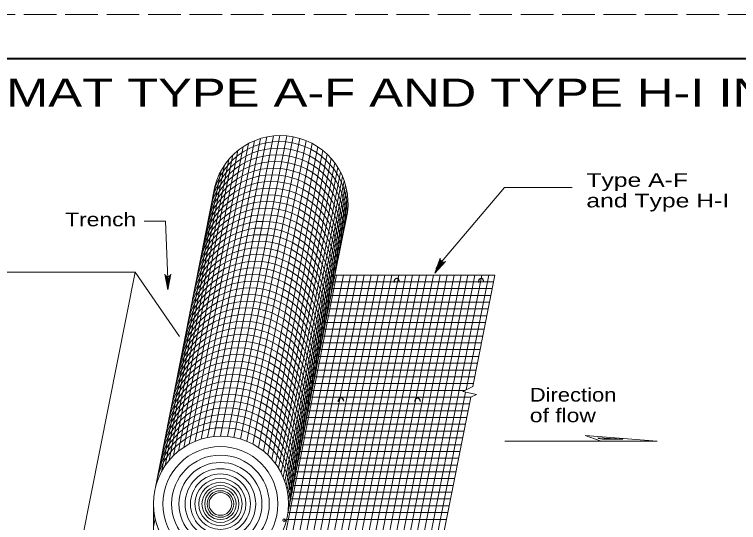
# Model space of a CAD drawing. Extents: x 1083.1 to 1117.1, y 719.4 to 741.4.
# Drawn here: x 1096.82 to 1105.08, y 735.56 to 741.35 of the extents above; entities that cross this region are included whole.
import ezdxf

# ---------------------------------------------------------------- set-up
doc = ezdxf.new("R2010")
doc.units = 0
doc.header["$LTSCALE"] = 0.062
doc.header["$PDMODE"] = 32
doc.header["$PDSIZE"] = 0.031
doc.linetypes.add('LONG_DASHED', pattern=[7.5, 6, -1.5])
doc.layers.add('1', color=7, linetype='Continuous', lineweight=13)

msp = doc.modelspace()

# ---------------------------------------------------------------- linework, layer by layer
at = {"layer": '1', "lineweight": 25}
msp.add_line((1085.12642, 740.85408), (1116.62642, 740.85408), dxfattribs=at)
at = {"layer": '1'}
for p, q in [((1098.88158, 736.48833), (1099.559, 739.91517)), ((1098.94975, 736.513), (1099.62717, 739.93983)), ((1099.0235, 736.53183), (1099.70092, 739.95867)), ((1099.09725, 736.54325), (1099.7745, 739.97008)), ((1099.84792, 739.97425), (1099.17058, 736.54742)), ((1099.25067, 736.544), (1099.928, 739.97083)), ((1100.00208, 739.96008), (1099.32475, 736.53325)), ((1100.07708, 739.94158), (1099.39975, 736.51475)), ((1100.15008, 739.9155), (1099.47275, 736.48883)), ((1099.43008, 739.84658), (1098.75275, 736.41975)), ((1099.49275, 739.88383), (1098.81542, 736.457)), ((1100.21842, 739.88317), (1099.541, 736.4565)), ((1100.28208, 739.845), (1099.60475, 736.41833)), ((1099.31375, 739.75233), (1098.63642, 736.3255)), ((1099.3705, 739.803), (1098.69317, 736.37608)), ((1100.33767, 739.80442), (1099.66042, 736.37767)), ((1100.38833, 739.76), (1099.711, 736.33333)), ((1099.26508, 739.69958), (1098.58775, 736.27275)), ((1100.43392, 739.71225), (1099.75667, 736.28558)), ((1100.47483, 739.66167), (1099.7975, 736.23492)), ((1099.21908, 739.63925), (1098.54175, 736.21233)), ((1100.511, 739.60833), (1099.83367, 736.18167)), ((1099.175, 739.5665), (1098.49758, 736.13958)), ((1100.53925, 739.55833), (1099.862, 736.13175)), ((1100.56325, 739.50792), (1099.88592, 736.08125)), ((1100.58292, 739.45725), (1099.9055, 736.03067)), ((1100.59725, 739.41183), (1099.91983, 735.98525)), ((1099.10767, 739.3925), (1098.43042, 735.96617)), ((1100.60892, 739.36417), (1099.93158, 735.9375)), ((1102.83092, 739.38158), (1103.17883, 739.38158)), ((1100.61792, 739.31358), (1099.94067, 735.88708)), ((1100.62392, 739.25808), (1099.94667, 735.83158)), ((1101.67958, 738.555), (1101.617, 738.40575)), ((1101.68633, 738.54467), (1101.617, 738.40575)), ((1101.69525, 738.5375), (1101.617, 738.40575)), ((1101.70908, 738.53258), (1101.617, 738.40575)), ((1101.72108, 738.5325), (1101.617, 738.40575)), ((1096.7415, 738.418), (1098.1975, 738.418)), ((1098.1975, 738.418), (1097.50425, 734.91067)), ((1098.7055, 737.68467), (1098.1975, 738.418)), ((1098.54892, 738.37575), (1098.57133, 738.21558)), ((1098.56, 738.37033), (1098.57133, 738.21558)), ((1098.59608, 738.37767), (1098.57133, 738.21558)), ((1098.58575, 738.3715), (1098.57133, 738.21558)), ((1098.57133, 738.36875), (1098.57133, 738.21558)), ((1099.82708, 735.00583), (1100.49425, 738.38117)), ((1099.90592, 735.00583), (1100.57317, 738.38117)), ((1099.98483, 735.00583), (1100.652, 738.38117)), ((1100.06375, 735.00583), (1100.73092, 738.38117)), ((1100.14258, 735.00583), (1100.80975, 738.38117)), ((1100.2215, 735.00583), (1100.88867, 738.38117)), ((1100.30033, 735.00583), (1100.9675, 738.38117)), ((1100.37925, 735.00583), (1101.04642, 738.38117)), ((1100.45808, 735.00583), (1101.12533, 738.38117)), ((1100.47708, 738.38117), (1102.2985, 738.38117)), ((1100.537, 735.00583), (1101.20417, 738.38117)), ((1100.61583, 735.00583), (1101.283, 738.38117)), ((1100.69475, 735.00583), (1101.36183, 738.38117)), ((1100.77367, 735.00583), (1101.44075, 738.38117)), ((1100.8525, 735.00583), (1101.51958, 738.38117)), ((1100.93142, 735.00583), (1101.5985, 738.38117)), ((1101.01025, 735.00583), (1101.67733, 738.38117)), ((1101.08917, 735.00583), (1101.75625, 738.38117)), ((1101.168, 735.00583), (1101.83517, 738.38117)), ((1101.24692, 735.00583), (1101.914, 738.38117)), ((1101.32575, 735.00583), (1101.99292, 738.38117)), ((1101.40467, 735.00583), (1102.07175, 738.38117)), ((1101.48358, 735.00583), (1102.15067, 738.38117)), ((1101.97133, 737.07483), (1102.2295, 738.38117)), ((1102.04758, 737.11175), (1102.2985, 738.38117)), ((1100.4625, 738.30692), (1102.28383, 738.30692)), ((1100.44717, 738.22958), (1102.2685, 738.22958)), ((1100.43192, 738.15217), (1102.25325, 738.15217)), ((1100.41667, 738.07483), (1102.23792, 738.07483)), ((1100.40133, 737.99742), (1102.22258, 737.99742)), ((1100.37075, 737.84267), (1102.19208, 737.84267)), ((1100.38608, 737.92008), (1102.20733, 737.92008)), ((1100.3555, 737.76533), (1102.17675, 737.76533)), ((1100.34017, 737.68792), (1102.1615, 737.68792)), ((1100.32483, 737.61058), (1102.14617, 737.61058)), ((1100.30958, 737.53317), (1102.13092, 737.53317)), ((1100.29425, 737.45583), (1102.11558, 737.45583)), ((1100.279, 737.3785), (1102.10025, 737.3785)), ((1100.26367, 737.30108), (1102.085, 737.30108)), ((1100.24842, 737.22375), (1102.06967, 737.22375)), ((1100.23317, 737.14633), (1102.05433, 737.14633)), ((1100.21783, 737.069), (1101.95925, 737.069)), ((1101.56233, 735.00583), (1101.96633, 737.04958)), ((1100.20258, 736.99158), (1102.02375, 736.99158)), ((1101.63133, 735.00583), (1102.02383, 736.99158)), ((1100.18725, 736.91425), (1102.00858, 736.91425)), ((1100.17192, 736.83683), (1101.99325, 736.83683)), ((1100.15667, 736.7595), (1101.97792, 736.7595)), ((1100.12608, 736.60475), (1101.94733, 736.60475)), ((1100.14133, 736.68208), (1101.96267, 736.68208)), ((1100.11075, 736.52733), (1101.932, 736.52733)), ((1100.09542, 736.45), (1101.91675, 736.45)), ((1100.08017, 736.37258), (1101.90142, 736.37258)), ((1100.06492, 736.29525), (1101.88608, 736.29525)), ((1100.04967, 736.21792), (1101.87083, 736.21792)), ((1100.03433, 736.1405), (1101.8555, 736.1405)), ((1100.019, 736.06317), (1101.84017, 736.06317)), ((1100.00375, 735.98575), (1101.825, 735.98575)), ((1099.98842, 735.90842), (1101.80967, 735.90842)), ((1098.40675, 735.77667), (1098.40675, 734.01492)), ((1099.97317, 735.831), (1101.79442, 735.831)), ((1098.40675, 735.71342), (1098.40867, 735.723)), ((1099.95783, 735.75367), (1101.77908, 735.75367)), ((1099.9425, 735.67625), (1101.76375, 735.67625)), ((1098.40675, 735.514), (1098.42542, 735.60842)), ((1099.92775, 735.59892), (1101.7485, 735.59892))]:
    msp.add_line(p, q, dxfattribs=at)
at = {"layer": '1', "linetype": 'LONG_DASHED'}
msp.add_lwpolyline([(1083.12642, 719.35408), (1117.12642, 719.35408), (1117.12642, 741.35408), (1083.12642, 741.35408)], close=True, dxfattribs=at)
at = {"layer": '1', "lineweight": 40}
msp.add_lwpolyline([(1085.12642, 740.85408), (1116.62642, 740.85408), (1116.62642, 719.85408), (1085.12642, 719.85408)], close=True, dxfattribs=at)
msp.add_lwpolyline([(1085.12642, 740.85408), (1116.62642, 740.85408), (1116.62642, 719.85408), (1085.12642, 719.85408)], close=True, dxfattribs=at)
at = {"layer": '1'}
for points in [[(1101.62608, 738.45817), (1102.41108, 739.38158), (1102.83092, 739.38158)], [(1100.61892, 739.09867), (1100.47708, 738.38117), (1099.94075, 735.66767)], [(1098.57417, 738.24617), (1098.54483, 738.997), (1098.30075, 738.997)], [(1101.73783, 738.53992), (1101.617, 738.40575), (1101.67692, 738.576)], [(1098.60675, 738.39258), (1098.57133, 738.21558), (1098.53592, 738.39258)], [(1102.0475, 737.11167), (1101.93375, 737.05667), (1102.08833, 737.02292), (1102.02375, 736.99158)], [(1102.41475, 736.49075), (1104.15083, 736.49075), (1103.32742, 736.55342), (1103.49875, 736.49333)], [(1103.47133, 736.52725), (1103.759, 736.51158), (1103.52583, 736.51158), (1103.47633, 736.522)]]:
    msp.add_lwpolyline(points, dxfattribs=at)
for centre, start, end in [((1101.71466, 738.57027), 171.38675, 307.21287), ((1098.57128, 738.40684), 202.08782, 337.91395)]:
    msp.add_arc(centre, 0.0382, start, end, dxfattribs=at)
for centre, major_axis, start_param, end_param in [((1099.85498, 739.20341), (0.7709, 0), 6.1469612, 9.1769689), ((1099.8414, 739.13534), (-0.77089, 0), 2.9997094, 6.0347974), ((1099.81141, 738.9836), (-0.77089, 0), 2.9997094, 6.0347974), ((1099.8264, 739.05947), (-0.77089, 0), 2.9997094, 6.0347974), ((1099.79642, 738.90772), (-0.77089, 0), 2.9997094, 6.0347974), ((1099.78143, 738.83185), (-0.77089, 0), 2.9997094, 6.0347974), ((1099.76643, 738.75598), (-0.77089, 0), 2.9997094, 6.0347974), ((1099.75144, 738.6801), (-0.77089, 0), 2.9997094, 6.0347974), ((1099.73645, 738.60423), (-0.77089, 0), 2.9997094, 6.0347974), ((1099.72145, 738.52836), (-0.77089, 0), 2.9997094, 6.0347974), ((1099.70646, 738.45248), (-0.77089, 0), 2.9997094, 6.0347974), ((1099.69139, 738.37661), (-0.77089, 0), 2.9997094, 6.0347974), ((1099.67639, 738.30074), (-0.77089, 0), 2.9997094, 6.0347974), ((1099.6614, 738.22487), (-0.77089, 0), 2.9997094, 6.0347974), ((1099.64641, 738.14899), (-0.77089, 0), 2.9997094, 6.0347974), ((1099.61642, 737.99725), (-0.77089, 0), 2.9997094, 6.0347974), ((1099.63141, 738.07312), (-0.77089, 0), 2.9997094, 6.0347974), ((1099.60143, 737.92137), (-0.77089, 0), 2.9997094, 6.0347974), ((1099.58643, 737.8455), (-0.77089, 0), 2.9997094, 6.0347974), ((1099.57144, 737.76963), (-0.77089, 0), 2.9997094, 6.0347974), ((1099.55645, 737.69376), (-0.77089, 0), 2.9997094, 6.0347974), ((1099.54146, 737.61788), (-0.77089, 0), 2.9997094, 6.0347974), ((1099.52646, 737.54201), (-0.77089, 0), 2.9997094, 6.0347974), ((1099.51147, 737.46614), (-0.77089, 0), 2.9997094, 6.0347974), ((1099.49648, 737.39026), (-0.77089, 0), 2.9997094, 6.0347974), ((1099.48148, 737.31439), (-0.77089, 0), 2.9997094, 6.0347974), ((1099.46649, 737.23852), (-0.77089, 0), 2.9997094, 6.0347974), ((1099.43651, 737.08677), (-0.77089, 0), 2.9997094, 6.0347974), ((1099.4515, 737.16264), (-0.77089, 0), 2.9997094, 6.0347974), ((1099.42151, 737.0109), (-0.77089, 0), 2.9997094, 6.0347974), ((1099.40652, 736.93503), (-0.77089, 0), 2.9997094, 6.0347974), ((1099.39153, 736.85915), (-0.77089, 0), 2.9997094, 6.0347974), ((1099.37653, 736.78328), (-0.77089, 0), 2.9997094, 6.0347974), ((1099.36154, 736.70741), (-0.77089, 0), 2.9997094, 6.0347974), ((1099.34655, 736.63153), (-0.77089, 0), 2.9997094, 6.0347974), ((1099.33155, 736.55566), (-0.77089, 0), 2.9997094, 6.0347974), ((1099.31656, 736.47979), (-0.77089, 0), 2.9997094, 6.0347974), ((1099.30157, 736.40392), (-0.77089, 0), 2.9997094, 6.0347974), ((1099.28658, 736.32804), (-0.77089, 0), 2.9997094, 6.0347974), ((1099.27158, 736.25217), (-0.77089, 0), 2.9997094, 6.0347974), ((1099.2416, 736.10042), (-0.77089, 0), 2.9997094, 6.0347974), ((1099.25659, 736.1763), (-0.77089, 0), 2.9997094, 6.0347974), ((1099.2266, 736.02455), (-0.77089, 0), 2.9997094, 6.0347974), ((1099.21161, 735.94868), (-0.77089, 0), 2.9997094, 6.0347974), ((1099.19662, 735.8728), (-0.77089, 0), 2.9997094, 6.0347974), ((1099.17843, 735.77701), (-0.77169, 0), 0.0004925, 0.6275136)]:
    msp.add_ellipse(centre, major_axis=major_axis, ratio=0.999895, start_param=start_param, end_param=end_param, dxfattribs=at)
at = {"layer": '1', "lineweight": 25}
for centre, major_axis, ratio, start_param, end_param in [((1101.1821, 738.30388), (-0.00492, 0.04069), 0.788117, 4.7123369, 7.8539295), ((1102.14348, 738.30355), (-0.00492, 0.04069), 0.788117, 4.7123369, 7.8539295), ((1100.54648, 736.94209), (-0.00492, 0.04069), 0.788117, 4.7123369, 7.8539295), ((1101.41865, 736.93958), (-0.00174, 0.04095), 0.788119, 4.7123704, 7.853963)]:
    msp.add_ellipse(centre, major_axis=major_axis, ratio=ratio, start_param=start_param, end_param=end_param, dxfattribs=at)
at = {"layer": '1'}
for centre, major_axis in [((1099.17771, 735.77663), (0.7709, 0)), ((1099.17084, 735.77408), (0.65527, 0)), ((1099.17083, 735.77408), (0.55698, 0)), ((1099.17083, 735.77407), (0.47343, 0)), ((1099.17082, 735.77407), (0.40242, 0)), ((1099.17082, 735.77407), (0.34205, 0)), ((1099.17082, 735.77407), (0.29075, 0)), ((1099.17081, 735.77406), (0.24713, 0)), ((1099.17081, 735.77406), (0.21006, 0)), ((1099.17081, 735.77406), (0.17855, 0)), ((1099.17081, 735.77406), (0.15177, 0)), ((1099.17081, 735.77406), (0.12901, 0))]:
    msp.add_ellipse(centre, major_axis=major_axis, ratio=0.999895, dxfattribs=at)
msp.add_point((1099.899, 735.59067), dxfattribs=at)

# ---------------------------------------------------------------- texts
for s, height, width, p in [('EROSION CONTROL MAT TYPE A-F AND TYPE H-I INSTALLATION', 0.32, 1.35, (1090.918, 740.30317)), ('Type A-F', 0.156, 1.35, (1103.34217, 739.38892)), ('and Type H-I', 0.156, 1.35, (1103.34217, 739.15492)), ('Trench', 0.156, 1.25, (1097.40042, 738.93933)), ('Direction', 0.156, 1.2, (1102.6975, 736.94117)), ('of flow', 0.156, 1.25, (1102.6975, 736.7065))]:
    msp.add_text(s, height=height, dxfattribs=dict(at, width=width)).set_placement(p)

doc.saveas('drawing.dxf')
